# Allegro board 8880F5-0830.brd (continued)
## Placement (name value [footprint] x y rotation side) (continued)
NOREF#2144  -  []  247.25 205.56 90 top
NOREF#2145  -  []  199.59 145.03 90 top
NOREF#2146  -  []  184.47 229.07 90 top
NOREF#2147  -  []  392.04 273.11 90 top
NOREF#2148  -  []  106.03 217.88 90 top
NOREF#2149  -  []  201.66 227.17 90 top
NOREF#2150  -  []  251.62 264.35 90 top
NOREF#2151  -  []  250.73 204.35 90 top
NOREF#2152  -  []  396.55 241.11 0 top
NOREF#2153  -  []  289.01 272.1 0 top
NOREF#2154  -  []  259.65 264.65 90 top
NOREF#2155  -  []  386.53 164.91 90 top
NOREF#2156  -  []  401.87 139.89 0 top
NOREF#2157  -  []  379.73 271.21 90 top
NOREF#2158  -  []  172.08 275.14 90 top
NOREF#2159  -  []  387.39 232.85 0 top
NOREF#2160  -  []  251.62 205.56 0 top
NOREF#2161  -  []  199.84 148.65 90 top
NOREF#2162  -  []  259.59 145.09 0 top
NOREF#2163  -  []  98.53 238.84 0 top
NOREF#2164  -  []  339.33 205.55 0 top
NOREF#2165  -  []  368.03 265.11 0 top
NOREF#2166  -  []  249.6 224.74 90 top
NOREF#2167  -  []  404.24 146.88 0 top
NOREF#2168  -  []  201.23 242.78 90 top
NOREF#2169  -  []  400.24 202.38 90 top
NOREF#2170  -  []  396.55 241.11 0 top
NOREF#2171  -  []  230.73 189.2 0 top
NOREF#2172  -  []  201.91 159.1 90 top
NOREF#2173  -  []  165.8 212.85 0 top
NOREF#2174  -  []  331.94 205.86 90 top
NOREF#2175  -  []  419.9 288.57 90 top
NOREF#2176  -  []  460.89 217.9 90 top
NOREF#2177  -  []  273.59 272.15 90 top
NOREF#2178  -  []  337.9 186.99 0 top
NOREF#2179  -  []  390.94 289.17 90 top
NOREF#2180  -  []  252.6 296.86 0 top
NOREF#2181  -  []  387.39 249.11 0 top
NOREF#2182  -  []  352.25 243.59 90 top
NOREF#2183  -  []  310.43 246.34 90 top
NOREF#2184  -  []  199.33 226.57 90 top
NOREF#2185  -  []  251.38 164.74 90 top
NOREF#2186  -  []  448.94 290.38 90 top
NOREF#2187  -  []  331.22 253.63 0 top
NOREF#2188  -  []  310.43 248.88 90 top
NOREF#2189  -  []  405.93 240.66 90 top
NOREF#2190  -  []  404.24 154.88 0 top
NOREF#2191  -  []  182.82 175.58 90 top
NOREF#2192  -  []  310.73 187.93 0 top
NOREF#2193  -  []  257.9 246.35 90 top
NOREF#2194  -  []  375.73 193.43 0 top
NOREF#2195  -  []  66.26 290.38 90 top
NOREF#2196  -  []  319.33 236.03 90 top
NOREF#2197  -  []  272.25 182.32 90 top
NOREF#2198  -  []  352.55 241.37 0 top
NOREF#2199  -  []  167.7 260.9 90 top
NOREF#2200  -  []  182.57 185.42 0 top
NOREF#2201  -  []  322.23 233.13 90 top
NOREF#2202  -  []  376.23 209.11 0 top
NOREF#2203  -  []  230.41 253.37 90 top
NOREF#2204  -  []  381.74 281.11 0 top
NOREF#2205  -  []  273.81 286.96 90 top
NOREF#2206  -  []  395.2 233.11 0 top
NOREF#2207  -  []  222.11 180.71 0 top
NOREF#2208  -  []  339.97 264.35 90 top
NOREF#2209  -  []  194.09 242.18 90 top
NOREF#2210  -  []  376.23 209.11 0 top
NOREF#2211  -  []  415.61 181.32 90 top
NOREF#2212  -  []  175.7 175.56 90 top
NOREF#2213  -  []  118.45 231.77 0 top
NOREF#2214  -  []  239.33 236.03 90 top
NOREF#2215  -  []  373.32 164.66 90 top
NOREF#2216  -  []  116.01 214.71 0 top
NOREF#2217  -  []  417.7 146.88 0 top
NOREF#2218  -  []  337.09 164.74 90 top
NOREF#2219  -  []  384.36 131.89 0 top
NOREF#2220  -  []  297.83 234.63 90 top
NOREF#2221  -  []  378.33 217.11 0 top
NOREF#2222  -  []  209.33 187.82 90 top
NOREF#2223  -  []  332.83 265.86 90 top
NOREF#2224  -  []  328.62 290.13 90 top
NOREF#2225  -  []  306.92 154.05 0 top
NOREF#2226  -  []  308.91 139.64 0 top
NOREF#2227  -  []  222.11 240.71 0 top
NOREF#2228  -  []  404.15 257.37 0 top
NOREF#2229  -  []  459.28 211.76 0 top
NOREF#2230  -  []  339.33 205.55 0 top
NOREF#2231  -  []  247.25 265.56 0 top
NOREF#2232  -  []  450.03 210.36 0 top
NOREF#2233  -  []  199.33 212.85 90 top
NOREF#2234  -  []  272.24 181.05 90 top
NOREF#2235  -  []  351.34 243.91 0 top
NOREF#2236  -  []  201.49 173.11 0 top
NOREF#2237  -  []  315.7 296.86 0 top
NOREF#2238  -  []  395.2 265.37 0 top
NOREF#2239  -  []  75.98 271.33 90 top
NOREF#2240  -  []  303.56 233.86 90 top
NOREF#2241  -  []  373.68 232.6 0 top
NOREF#2242  -  []  418.38 131.89 0 top
NOREF#2243  -  []  397.38 180.15 90 top
NOREF#2244  -  []  247.57 265.86 90 top
NOREF#2245  -  []  463.11 186.77 0 top
NOREF#2246  -  []  263.71 288.86 0 top
NOREF#2247  -  []  461.86 187.32 0 top
NOREF#2248  -  []  373.87 171.39 0 top
NOREF#2249  -  []  167.7 247.18 90 top
NOREF#2250  -  []  330.73 265.56 90 top
NOREF#2251  -  []  167.7 165.4 90 top
NOREF#2252  -  []  104.18 191.95 90 top
NOREF#2253  -  []  188.08 291.65 90 top
NOREF#2254  -  []  314.71 129.74 90 top
NOREF#2255  -  []  310.73 186.66 0 top
NOREF#2256  -  []  333.4 204.35 90 top
NOREF#2257  -  []  383.09 257.11 0 top
NOREF#2258  -  []  217.41 213.24 0 top
NOREF#2259  -  []  397.8 179.6 90 top
NOREF#2260  -  []  327.7 131.09 90 top
NOREF#2261  -  []  229.21 248.88 0 top
NOREF#2262  -  []  272.25 185.5 0 top
NOREF#2263  -  []  84.04 290.38 90 top
NOREF#2264  -  []  390.69 257.11 0 top
NOREF#2265  -  []  331.06 223.82 90 top
NOREF#2266  -  []  341.63 195.43 90 top
NOREF#2267  -  []  495.08 274.77 90 top
NOREF#2268  -  []  376.23 209.11 0 top
NOREF#2269  -  []  378.75 240.66 90 top
NOREF#2270  -  []  470.71 227 90 top
NOREF#2271  -  []  310.83 164.63 0 top
NOREF#2272  -  []  167.7 138.47 90 top
NOREF#2273  -  []  473.7 219.66 90 top
NOREF#2274  -  []  382.82 163.39 0 top
NOREF#2275  -  []  378.75 224.15 90 top
NOREF#2276  -  []  342.36 223.82 90 top
NOREF#2277  -  []  414.82 249.11 0 top
NOREF#2278  -  []  254.29 265.56 0 top
NOREF#2279  -  []  223.56 173.86 90 top
NOREF#2280  -  []  375.22 180.15 0 top
NOREF#2281  -  []  371.48 224.6 0 top
NOREF#2282  -  []  272.25 189.18 90 top
NOREF#2283  -  []  168.13 213.45 90 top
NOREF#2284  -  []  201.23 241.43 0 top
NOREF#2285  -  []  392.24 196.98 90 top
NOREF#2286  -  []  264.29 280.1 0 top
NOREF#2287  -  []  405.93 272.56 90 top
NOREF#2288  -  []  237.66 164.72 0 top
NOREF#2289  -  []  229.51 247.93 0 top
NOREF#2290  -  []  229.21 188.88 0 top
NOREF#2291  -  []  317.98 223.82 90 top
NOREF#2292  -  []  419.9 240.66 90 top
NOREF#2293  -  []  451.64 222.5 0 top
NOREF#2294  -  []  290.64 288.86 0 top
NOREF#2295  -  []  403.41 209.61 0 top
NOREF#2296  -  []  473.7 176.22 90 top
NOREF#2297  -  []  354.27 138.37 90 top
NOREF#2298  -  []  262.68 224.74 90 top
NOREF#2299  -  []  165.8 240.28 90 top
NOREF#2300  -  []  272.8 145.48 90 top
NOREF#2301  -  []  199.59 158.5 0 top
NOREF#2302  -  []  411.26 163.19 90 top
NOREF#2303  -  []  450.03 191.31 0 top
NOREF#2304  -  []  309.21 247.61 0 top
NOREF#2305  -  []  412.62 297.12 0 top
NOREF#2306  -  []  272.24 182.32 90 top
NOREF#2307  -  []  165.8 144.78 90 top
NOREF#2308  -  []  392.47 256.66 90 top
NOREF#2309  -  []  331.94 204.65 90 top
NOREF#2310  -  []  199.08 254 0 top
NOREF#2311  -  []  330.73 265.56 0 top
NOREF#2312  -  []  274.67 286.96 0 top
NOREF#2313  -  []  449.99 217.9 0 top
NOREF#2314  -  []  319.33 183.63 90 top
NOREF#2315  -  []  271.04 245.5 0 top
NOREF#2316  -  []  230.41 193.37 90 top
NOREF#2317  -  []  250.49 223.52 90 top
NOREF#2318  -  []  229.51 243.41 0 top
NOREF#2319  -  []  295.96 177.06 0 top
NOREF#2320  -  []  301.56 171.46 0 top
NOREF#2321  -  []  392.24 194.78 90 top
NOREF#2322  -  []  218.13 274.06 0 top
NOREF#2323  -  []  184.47 260.9 90 top
NOREF#2324  -  []  394.66 258.64 90 top
NOREF#2325  -  []  221.56 182.89 0 top
NOREF#2326  -  []  184.89 199.99 90 top
NOREF#2327  -  []  369.38 241.11 0 top
NOREF#2328  -  []  321.35 296.86 0 top
NOREF#2329  -  []  184.47 147.28 90 top
NOREF#2330  -  []  301.56 231.46 0 top
NOREF#2331  -  []  250.5 288.86 0 top
NOREF#2332  -  []  216.96 180.71 0 top
NOREF#2333  -  []  405.93 256.82 90 top
NOREF#2334  -  []  262.68 163.52 90 top
NOREF#2335  -  []  271.34 249.5 0 top
NOREF#2336  -  []  312.21 131.64 0 top
NOREF#2337  -  []  167.7 244.98 90 top
NOREF#2338  -  []  182.82 162.12 90 top
NOREF#2339  -  []  403.41 209.61 0 top
NOREF#2340  -  []  265.81 296.86 0 top
NOREF#2341  -  []  415.6 146.88 0 top
NOREF#2342  -  []  253.53 140.14 0 top
NOREF#2343  -  []  167.7 159.65 0 top
NOREF#2344  -  []  310.73 189.2 0 top
NOREF#2345  -  []  341.63 233.83 90 top
NOREF#2346  -  []  283.25 147.43 90 top
NOREF#2347  -  []  175.7 243.88 90 top
NOREF#2348  -  []  296.96 180.71 0 top
NOREF#2349  -  []  342.04 164.72 0 top
NOREF#2350  -  []  272.25 244.23 0 top
NOREF#2351  -  []  101.29 247.16 90 top
NOREF#2352  -  []  229.21 186.34 0 top
NOREF#2353  -  []  310.43 253.37 90 top
NOREF#2354  -  []  115.87 175.44 90 top
NOREF#2355  -  []  396.03 146.88 0 top
NOREF#2356  -  []  331.54 192.73 90 top
NOREF#2357  -  []  471.21 168.33 0 top
NOREF#2358  -  []  383.73 202.38 90 top
NOREF#2359  -  []  110.21 195.15 0 top
NOREF#2360  -  []  459.24 219.3 90 top
NOREF#2361  -  []  313.56 131.64 90 top
NOREF#2362  -  []  328.01 286.96 0 top
NOREF#2363  -  []  385.32 161.49 90 top
NOREF#2364  -  []  201.23 215.35 90 top
NOREF#2365  -  []  263.31 164.74 0 top
NOREF#2366  -  []  192.47 168.6 90 top
NOREF#2367  -  []  343.98 288.86 0 top
NOREF#2368  -  []  298.16 248.49 0 top
NOREF#2369  -  []  250.74 224.72 0 top
NOREF#2370  -  []  242.23 173.13 0 top
NOREF#2371  -  []  247.57 264.65 90 top
NOREF#2372  -  []  352.24 249.18 90 top
NOREF#2373  -  []  352.25 183.59 90 top
NOREF#2374  -  []  271.34 189.5 0 top
NOREF#2375  -  []  229.51 193.69 0 top
NOREF#2376  -  []  115.61 219.13 90 top
NOREF#2377  -  []  425.7 144.98 90 top
NOREF#2378  -  []  231.15 159.63 90 top
NOREF#2379  -  []  263.83 231.63 90 top
NOREF#2380  -  []  449.99 174.46 0 top
NOREF#2381  -  []  409.99 146.93 90 top
NOREF#2382  -  []  265.81 288.86 0 top
NOREF#2383  -  []  272.25 189.82 0 top
NOREF#2384  -  []  272.25 183.59 90 top
NOREF#2385  -  []  166.06 148.4 90 top
NOREF#2386  -  []  338.36 288.91 90 top
NOREF#2387  -  []  406.19 171.64 0 top
NOREF#2388  -  []  175.7 148.38 90 top
NOREF#2389  -  []  279.7 155.38 0 top
NOREF#2390  -  []  215.96 248.49 0 top
NOREF#2391  -  []  518.38 257.36 90 top
NOREF#2392  -  []  260.83 174.63 90 top
NOREF#2393  -  []  330.73 205.55 0 top
NOREF#2394  -  []  177.33 146.68 90 top
NOREF#2395  -  []  410.52 241.11 0 top
NOREF#2396  -  []  211.11 160.4 90 top
NOREF#2397  -  []  155.57 272.6 90 top
NOREF#2398  -  []  185.2 290.01 90 top
NOREF#2399  -  []  415.61 183.52 90 top
NOREF#2400  -  []  259.45 288.86 90 top
NOREF#2401  -  []  248 286.96 0 top
NOREF#2402  -  []  94.68 234.24 0 top
NOREF#2403  -  []  199.59 189.04 90 top
NOREF#2404  -  []  331.05 204.65 90 top
NOREF#2405  -  []  384.36 131.89 0 top
NOREF#2406  -  []  175.7 230.17 90 top
NOREF#2407  -  []  304.82 146.05 0 top
NOREF#2408  -  []  209.59 160.9 90 top
NOREF#2409  -  []  257.9 186.35 90 top
NOREF#2410  -  []  259.33 205.56 0 top
NOREF#2411  -  []  351.04 249.82 0 top
NOREF#2412  -  []  246.63 130.24 90 top
NOREF#2413  -  []  184.47 255.15 90 top
NOREF#2414  -  []  296.96 252.14 0 top
NOREF#2415  -  []  252.51 205.55 0 top
NOREF#2416  -  []  209.08 256.4 90 top
NOREF#2417  -  []  327.25 265.56 90 top
NOREF#2418  -  []  230.41 188.88 90 top
NOREF#2419  -  []  184.47 244.98 90 top
NOREF#2420  -  []  391.8 209.36 0 top
NOREF#2421  -  []  354.08 286.96 90 top
NOREF#2422  -  []  342.68 163.52 90 top
NOREF#2423  -  []  267.84 280.1 0 top
NOREF#2424  -  []  327.57 204.65 90 top
NOREF#2425  -  []  230.43 248.88 90 top
NOREF#2426  -  []  376.15 192.88 90 top
NOREF#2427  -  []  451.64 179.06 0 top
NOREF#2428  -  []  375.73 193.43 90 top
NOREF#2429  -  []  419.9 272.92 90 top
NOREF#2430  -  []  237.57 269.63 90 top
NOREF#2431  -  []  177.33 160.4 90 top
NOREF#2432  -  []  201.49 173.11 90 top
NOREF#2433  -  []  199.33 199.39 90 top
NOREF#2434  -  []  110.21 214.71 0 top
NOREF#2435  -  []  182.57 226.57 0 top
NOREF#2436  -  []  259.33 264.35 90 top
NOREF#2437  -  []  112.67 171.02 0 top
NOREF#2438  -  []  401.89 180.15 0 top
NOREF#2439  -  []  185.2 276.04 90 top
NOREF#2440  -  []  201.23 204.09 90 top
NOREF#2441  -  []  175.8 160.9 90 top
NOREF#2442  -  []  390.69 241.11 0 top
NOREF#2443  -  []  336.77 225.04 90 top
NOREF#2444  -  []  263.71 288.86 0 top
NOREF#2445  -  []  352.25 181.69 0 top
NOREF#2446  -  []  310.73 249.2 0 top
NOREF#2447  -  []  93.76 290.38 90 top
NOREF#2448  -  []  192.47 232.37 90 top
NOREF#2449  -  []  401.89 180.15 0 top
NOREF#2450  -  []  398.53 161.74 90 top
NOREF#2451  -  []  167.7 186.57 0 top
NOREF#2452  -  []  247.25 265.56 90 top
NOREF#2453  -  []  120.21 178.64 0 top
NOREF#2454  -  []  211.11 146.93 90 top
NOREF#2455  -  []  251.62 265.55 0 top
NOREF#2456  -  []  192.47 154.88 90 top
NOREF#2457  -  []  165.8 226.57 90 top
NOREF#2458  -  []  352.55 183.91 0 top
NOREF#2459  -  []  330.73 204.35 90 top
NOREF#2460  -  []  272.55 249.5 0 top
NOREF#2461  -  []  324.65 288.86 0 top
NOREF#2462  -  []  462.06 293.82 90 top
NOREF#2463  -  []  108.01 214.71 0 top
NOREF#2464  -  []  317.66 164.72 0 top
NOREF#2465  -  []  327.25 265.56 0 top
NOREF#2466  -  []  310.43 186.34 90 top
NOREF#2467  -  []  251.33 140.14 0 top
NOREF#2468  -  []  215.96 177.06 0 top
NOREF#2469  -  []  272.24 244.86 90 top
NOREF#2470  -  []  412.88 139.89 0 top
NOREF#2471  -  []  302.11 252.14 0 top
NOREF#2472  -  []  229.21 246.34 0 top
NOREF#2473  -  []  409.74 163.69 90 top
NOREF#2474  -  []  218.13 214.06 0 top
NOREF#2475  -  []  184.47 187.92 90 top
NOREF#2476  -  []  259.33 205.56 90 top
NOREF#2477  -  []  328.96 224.72 0 top
NOREF#2478  -  []  395.07 129.99 0 top
NOREF#2479  -  []  230.43 186.34 0 top
NOREF#2480  -  []  453.88 186.77 0 top
NOREF#2481  -  []  399.07 208.81 90 top
NOREF#2482  -  []  412.79 209.06 90 top
NOREF#2483  -  []  221.56 171.46 0 top
NOREF#2484  -  []  254.29 265.56 90 top
NOREF#2485  -  []  414.25 154.88 0 top
NOREF#2486  -  []  184.47 176.66 90 top
NOREF#2487  -  []  175.7 205.19 90 top
NOREF#2488  -  []  310.41 247.61 90 top
NOREF#2489  -  []  221.56 190.49 0 top
NOREF#2490  -  []  247.57 264.65 90 top
NOREF#2491  -  []  411.01 209.61 0 top
NOREF#2492  -  []  410.84 180.15 90 top
NOREF#2493  -  []  118.45 231.77 0 top
NOREF#2494  -  []  257.9 246.99 0 top
NOREF#2495  -  []  175.8 215.25 90 top
NOREF#2496  -  []  375.73 199.18 90 top
NOREF#2497  -  []  388.43 180.15 0 top
NOREF#2498  -  []  194.09 201.29 90 top
NOREF#2499  -  []  302.11 192.14 0 top
NOREF#2500  -  []  419.47 289.12 90 top
NOREF#2501  -  []  200.98 256.5 90 top
NOREF#2502  -  []  392.47 288.67 90 top
NOREF#2503  -  []  409.74 180.2 90 top
NOREF#2504  -  []  215.96 188.49 0 top
NOREF#2505  -  []  351.04 249.18 0 top
NOREF#2506  -  []  175.7 232.37 90 top
NOREF#2507  -  []  397.8 146.33 90 top
NOREF#2508  -  []  343.2 232.26 90 top
NOREF#2509  -  []  334.61 204.65 90 top
NOREF#2510  -  []  410.78 131.89 0 top
NOREF#2511  -  []  172.08 289.11 90 top
NOREF#2512  -  []  248.61 290.13 90 top
NOREF#2513  -  []  246.63 142.04 0 top
NOREF#2514  -  []  371.73 297.12 0 top
NOREF#2515  -  []  310.73 183.41 0 top
NOREF#2516  -  []  106.76 222.88 0 top
NOREF#2517  -  []  167.7 206.29 90 top
NOREF#2518  -  []  240.94 211.63 90 top
NOREF#2519  -  []  418.12 257.42 90 top
NOREF#2520  -  []  167.7 219.75 90 top
NOREF#2521  -  []  400.54 171.64 0 top
NOREF#2522  -  []  308.14 296.86 0 top
NOREF#2523  -  []  253.4 265.55 0 top
NOREF#2524  -  []  380.59 239.21 0 top
NOREF#2525  -  []  240.83 254.63 0 top
NOREF#2526  -  []  330.17 223.82 90 top
NOREF#2527  -  []  412.62 273.37 0 top
NOREF#2528  -  []  309.51 186.66 0 top
NOREF#2529  -  []  192.57 242.68 90 top
NOREF#2530  -  []  256.45 164.74 0 top
NOREF#2531  -  []  165.8 158.5 90 top
NOREF#2532  -  []  246.67 288.16 90 top
NOREF#2533  -  []  330.74 164.72 0 top
NOREF#2534  -  []  405.93 224.66 90 top
NOREF#2535  -  []  456.08 195.91 0 top
NOREF#2536  -  []  262.36 223.82 90 top
NOREF#2537  -  []  184.89 213.45 90 top
NOREF#2538  -  []  184.47 247.18 90 top
NOREF#2539  -  []  453.88 171.53 0 top
NOREF#2540  -  []  321.82 167.13 90 top
NOREF#2541  -  []  112.16 238.84 0 top
NOREF#2542  -  []  201.49 174.46 90 top
NOREF#2543  -  []  260.74 143.19 0 top
NOREF#2544  -  []  252.43 132.14 0 top
NOREF#2545  -  []  118.7 222.88 0 top
NOREF#2546  -  []  450.03 182.17 0 top
NOREF#2547  -  []  230.73 186.66 0 top
NOREF#2548  -  []  251.86 192.43 90 top
NOREF#2549  -  []  271.04 184.23 0 top
NOREF#2550  -  []  277.17 288.86 0 top
NOREF#2551  -  []  184.47 151.68 90 top
NOREF#2552  -  []  463.61 214.96 0 top
NOREF#2553  -  []  211.11 173.86 90 top
NOREF#2554  -  []  127.99 214.79 0 top
NOREF#2555  -  []  167.7 219.75 90 top
NOREF#2556  -  []  128.24 171.1 0 top
NOREF#2557  -  []  302.49 296.86 0 top
NOREF#2558  -  []  167.7 256.5 90 top
NOREF#2559  -  []  96.58 195.15 0 top
NOREF#2560  -  []  279.7 155.38 0 top
NOREF#2561  -  []  322.23 173.13 90 top
NOREF#2562  -  []  456.08 171.53 0 top
NOREF#2563  -  []  230.41 246.34 90 top
NOREF#2564  -  []  396.55 289.12 0 top
NOREF#2565  -  []  200.98 260.9 90 top
NOREF#2566  -  []  470.71 183.57 90 top
NOREF#2567  -  []  230.43 246.34 90 top
NOREF#2568  -  []  199.59 145.03 0 top
NOREF#2569  -  []  518.38 273.87 90 top
NOREF#2570  -  []  278.6 147.38 0 top
NOREF#2571  -  []  398.65 225.11 0 top
NOREF#2572  -  []  394.05 239.21 0 top
R1  NC/1M-1-S4  [R0402]  221.23 227.84 180 bottom
R2  NC/1M-1-S4  [R0402]  218.95 227.84 0 bottom
R3  NC/100K-1-S4  [R0402]  184.15 131.06 180 bottom
R4  NC/100K-1-S4  [R0402]  181.61 131.06 180 bottom
R5  0-5-S4  [R0402]  222.38 272.16 270 bottom
R6  1M-1-S4  [R0402]  222.38 274.32 270 bottom
R7  49.9-1-S4  [R0402]  349.4 299.66 180 bottom
R8  49.9-1-S4  [R0402]  351.55 299.66 180 bottom
R9  49.9-1-S4  [R0402]  349.4 286.07 180 bottom
R10  49.9-1-S4  [R0402]  351.55 286.07 180 bottom
R11  49.9-1-S4  [R0402]  335.94 299.66 180 bottom
R12  49.9-1-S4  [R0402]  338.09 299.66 180 bottom
R13  49.9-1-S4  [R0402]  335.94 286.07 180 bottom
R14  49.9-1-S4  [R0402]  338.09 286.07 180 bottom
R15  49.9-1-S4  [R0402]  322.48 299.66 180 bottom
R16  49.9-1-S4  [R0402]  324.62 299.66 180 bottom
R17  49.9-1-S4  [R0402]  322.48 286.07 180 bottom
R18  49.9-1-S4  [R0402]  324.62 286.07 180 bottom
R19  49.9-1-S4  [R0402]  287.88 269.3 0 bottom
R20  49.9-1-S4  [R0402]  285.74 269.3 0 bottom
R21  49.9-1-S4  [R0402]  287.88 282.89 0 bottom
R22  49.9-1-S4  [R0402]  285.74 282.89 0 bottom
R23  49.9-1-S4  [R0402]  309.27 299.66 180 bottom
R24  49.9-1-S4  [R0402]  311.42 299.66 180 bottom
R25  49.9-1-S4  [R0402]  309.27 286.07 180 bottom
R26  49.9-1-S4  [R0402]  311.42 286.07 180 bottom
R27  49.9-1-S4  [R0402]  296.06 299.66 180 bottom
R28  49.9-1-S4  [R0402]  298.21 299.66 180 bottom
R29  49.9-1-S4  [R0402]  296.06 286.07 180 bottom
R30  49.9-1-S4  [R0402]  298.21 286.07 180 bottom
R31  49.9-1-S4  [R0402]  282.6 299.66 180 bottom
R32  49.9-1-S4  [R0402]  284.75 299.66 180 bottom
R33  49.9-1-S4  [R0402]  282.6 286.07 180 bottom
R34  49.9-1-S4  [R0402]  284.75 286.07 180 bottom
R37  49.9-1-S4  [R0402]  269.14 286.07 180 bottom
R38  49.9-1-S4  [R0402]  271.28 286.07 180 bottom
R39  49.9-1-S4  [R0402]  255.93 299.66 180 bottom
R40  49.9-1-S4  [R0402]  258.08 299.66 180 bottom
R41  49.9-1-S4  [R0402]  255.93 286.07 180 bottom
R42  49.9-1-S4  [R0402]  258.08 286.07 180 bottom
R43  49.9-1-S4  [R0402]  164.91 258.67 90 bottom
R44  49.9-1-S4  [R0402]  164.91 256.53 90 bottom
R45  49.9-1-S4  [R0402]  198.44 231.24 90 bottom
R46  49.9-1-S4  [R0402]  198.44 229.1 90 bottom
R47  49.9-1-S4  [R0402]  178.5 217.52 90 bottom
R48  49.9-1-S4  [R0402]  178.5 215.38 90 bottom
R49  49.9-1-S4  [R0402]  164.91 217.52 90 bottom
R50  49.9-1-S4  [R0402]  164.91 215.38 90 bottom
R51  49.9-1-S4  [R0402]  195.26 231.24 90 bottom
R52  49.9-1-S4  [R0402]  195.26 229.1 90 bottom
R53  49.9-1-S4  [R0402]  181.67 231.24 90 bottom
R54  49.9-1-S4  [R0402]  181.67 229.1 90 bottom
R55  49.9-1-S4  [R0402]  212.03 244.96 90 bottom
R56  49.9-1-S4  [R0402]  212.03 242.81 90 bottom
R57  49.9-1-S4  [R0402]  198.44 244.96 90 bottom
R58  49.9-1-S4  [R0402]  198.44 242.81 90 bottom
R59  49.9-1-S4  [R0402]  178.5 231.24 90 bottom
R60  49.9-1-S4  [R0402]  178.5 229.1 90 bottom
R61  49.9-1-S4  [R0402]  164.91 231.24 90 bottom
R62  49.9-1-S4  [R0402]  164.91 229.1 90 bottom
R63  49.9-1-S4  [R0402]  178.5 244.96 90 bottom
R64  49.9-1-S4  [R0402]  178.5 242.81 90 bottom
R65  49.9-1-S4  [R0402]  181.67 244.96 90 bottom
R66  49.9-1-S4  [R0402]  181.67 242.81 90 bottom
R67  49.9-1-S4  [R0402]  239.37 285.81 0 bottom
R68  49.9-1-S4  [R0402]  237.22 285.81 0 bottom
R69  49.9-1-S4  [R0402]  239.37 299.4 0 bottom
R70  49.9-1-S4  [R0402]  237.22 299.4 0 bottom
R71  49.9-1-S4  [R0402]  195.26 258.67 90 bottom
R72  49.9-1-S4  [R0402]  195.26 256.53 90 bottom
R73  49.9-1-S4  [R0402]  181.67 258.67 90 bottom
R74  49.9-1-S4  [R0402]  181.67 256.53 90 bottom
R75  49.9-1-S4  [R0402]  211.77 258.67 90 bottom
R76  49.9-1-S4  [R0402]  211.77 256.53 90 bottom
R77  49.9-1-S4  [R0402]  198.18 258.67 90 bottom
R78  49.9-1-S4  [R0402]  198.18 256.53 90 bottom
R79  49.9-1-S4  [R0402]  178.5 258.67 90 bottom
R80  49.9-1-S4  [R0402]  178.5 256.53 90 bottom
R82  4.7K-1-S4-WA  [R0402]  122.62 241.1 180 bottom
R83  4.7K-1-S4-WA  [R0402]  96.77 233.43 180 bottom
R84  4.7K-1-S4-WA  [R0402]  96.77 241.05 180 bottom
R85  100K-1-S4  [R0402]  113.79 230.12 180 bottom
R86  4.7K-1-S4-WA  [R0402]  93.33 207.46 180 bottom
R87  4.7K-1-S4-WA  [R0402]  104.14 203.31 180 bottom
R88  4.7K-1-S4-WA  [R0402]  101.6 203.31 180 bottom
R89  4.7K-1-S4-WA  [R0402]  89.03 207.41 0 bottom
R90  4.7K-1-S4-WA  [R0402]  101.6 215.5 180 bottom
R91  4.7K-1-S4-WA  [R0402]  99.06 215.5 180 bottom
R92  4.7K-1-S4-WA  [R0402]  96.52 215.5 180 bottom
R93  4.7K-1-S4-WA  [R0402]  93.33 221.18 180 bottom
R94  4.7K-1-S4-WA  [R0402]  104.25 216.86 0 bottom
R95  4.7K-1-S4-WA  [R0402]  101.7 216.91 180 bottom
R96  4.7K-1-S4-WA  [R0402]  89.27 221.18 0 bottom
R97  4.7K-1-S4-WA  [R0402]  101.7 229.1 180 bottom
R98  4.7K-1-S4-WA  [R0402]  99.16 229.1 180 bottom
R99  4.7K-1-S4-WA  [R0402]  96.62 229.1 180 bottom
R100  49.9-1-S4  [R0402]  164.91 244.96 90 bottom
R101  49.9-1-S4  [R0402]  164.91 242.81 90 bottom
R102  49.9-1-S4  [R0402]  212.03 231.24 90 bottom
R103  49.9-1-S4  [R0402]  212.03 229.1 90 bottom
R104  49.9-1-S4  [R0402]  195.26 244.96 90 bottom
R105  49.9-1-S4  [R0402]  195.26 242.81 90 bottom
R117  1K-1-S4  [R0402]  127.2 241.1 180 bottom
R118  NC/0-5-S4  [R0402]  230.41 245.39 180 bottom
R119  4.7K-1-S4-WA  [R0402]  127.25 233.43 0 bottom
R120  4.7K-1-S4-WA  [R0402]  127.25 225.81 0 bottom
R125  0-5-S4  [R0402]  123.19 224.54 180 bottom
R126  0-5-S4  [R0402]  127.25 224.54 180 bottom
R127  0-5-S4  [R0402]  122.94 216.92 180 bottom
R128  0-5-S4  [R0402]  127.51 216.92 180 bottom
R129  0-5-S4  [R0402]  221.23 229.11 180 bottom
R130  0-5-S4  [R0402]  218.95 229.11 0 bottom
R131  50-0.1-S4-HF-VI  [R0402]  223.77 243.33 90 bottom
R132  50-0.1-S4-HF-VI  [R0402]  216.15 243.33 90 bottom
R133  0-5-S4  [R0402]  222.38 276.48 90 bottom
RB1  10K-1-S6  [R0603]  212.47 13.59 0 bottom
RB2  10K-1-S6  [R0603]  212.47 12.06 0 bottom
S1_I2C  HDR-4X1-MR-A  [JP_4P_100_R90_V1]  62.99 209.04 270 top
S1_RST_N  HDR-2X1-M  [JP_2P_100]  115.82 232.41 270 bottom
S2_I2C  HDR-4X1-MR-A  [JP_4P_100_R90_V1]  497.33 203.45 270 top
S2_RST_N  HDR-2X1-M  [JP_2P_100]  463.04 233.43 90 bottom
S3_I2C  HDR-4X1-MR-A  [JP_4P_100_R90_V1]  75.69 209.04 270 top
S3_RST_N  HDR-2X1-M  [JP_2P_100]  116.08 188.72 270 bottom
S4_I2C  HDR-4X1-MR-A  [JP_4P_100_R90_V1]  511.3 203.45 270 top
S4_RST_N  HDR-2X1-M  [JP_2P_100]  463.04 189.99 90 bottom
SB1  SHORT  [DEFAULT_SHORT_SMALL]  402.59 11.04 90 top
SB2  SHORT  [DEFAULT_SHORT_SMALL]  328.93 417.83 270 top
SB3  SHORT  [DEFAULT_SHORT_SMALL]  255.27 11.71 90 top
SB8  SHORT  [DEFAULT_SHORT_SMALL]  179.07 418.32 270 top
SCREW1  V93KMFHOLE  [PG_VG93K_F_FULLOUTLINE]  290.83 214.63 0 top
SH1  SHORT  [DEFAULT_SHORT_SMALL]  185.19 290.72 0 top
SH2  SHORT  [DEFAULT_SHORT_SMALL]  187.14 290.72 0 top
SH3  SHORT  [DEFAULT_SHORT_SMALL]  175.35 290.72 0 top
SH4  SHORT  [DEFAULT_SHORT_SMALL]  173.4 290.85 180 top
SH5  SHORT  [DEFAULT_SHORT_SMALL]  118.2 289.45 0 top
SH6  SHORT  [DEFAULT_SHORT_SMALL]  116.25 289.58 180 top
SH7  SHORT  [DEFAULT_SHORT_SMALL]  168.68 290.72 0 top
SH8  SHORT  [DEFAULT_SHORT_SMALL]  156.89 290.85 180 top
SH9  SHORT  [DEFAULT_SHORT_SMALL]  170.63 290.72 0 top
SH10  SHORT  [DEFAULT_SHORT_SMALL]  158.84 290.72 0 top
SH11  SHORT  [DEFAULT_SHORT_SMALL]  173.4 274.34 180 top
SH12  SHORT  [DEFAULT_SHORT_SMALL]  185.19 274.21 0 top
SH13  SHORT  [DEFAULT_SHORT_SMALL]  203.14 290.72 0 top
SH14  SHORT  [DEFAULT_SHORT_SMALL]  201.19 290.72 0 top
SH15  SHORT  [DEFAULT_SHORT_SMALL]  189.4 290.85 180 top
SH16  SHORT  [DEFAULT_SHORT_SMALL]  191.35 290.72 0 top
SH17  SHORT  [DEFAULT_SHORT_SMALL]  156.89 274.34 180 top
SH18  SHORT  [DEFAULT_SHORT_SMALL]  168.68 274.21 0 top
SH19  SHORT  [DEFAULT_SHORT_SMALL]  99.42 246.45 0 top
SH20  SHORT  [DEFAULT_SHORT_SMALL]  101.62 246.45 0 top
SH21  SHORT  [DEFAULT_SHORT_SMALL]  94.56 246.5 0 top
SH22  SHORT  [DEFAULT_SHORT_SMALL]  96.76 246.5 0 top
SH23  SHORT  [DEFAULT_SHORT_SMALL]  201.19 274.21 0 top
SH24  SHORT  [DEFAULT_SHORT_SMALL]  203.37 274.08 180 top
SH25  SHORT  [DEFAULT_SHORT_SMALL]  175.35 274.21 0 top
SH26  SHORT  [DEFAULT_SHORT_SMALL]  187.14 274.21 0 top
SH27  SHORT  [DEFAULT_SHORT_SMALL]  158.84 274.21 0 top
SH28  SHORT  [DEFAULT_SHORT_SMALL]  170.63 274.21 0 top
SITE1  CU/HX8880-F05-LQFP176-20X20  [SK_LQFP176P_0P4MM_JG_HX8880]  250.83 244.63 90 top
SITE2  CU/HX8880-F05-LQFP176-20X20  [SK_LQFP176P_0P4MM_JG_HX8880]  330.83 244.63 90 top
SITE3  CU/HX8880-F05-LQFP176-20X20  [SK_LQFP176P_0P4MM_JG_HX8880]  250.83 184.63 90 top
SITE4  CU/HX8880-F05-LQFP176-20X20  [SK_LQFP176P_0P4MM_JG_HX8880]  330.83 184.63 90 top
SKB  Socket_Base_M5_140x140  [SOCKET_BASE_140X140_565100]  290.83 214.63 0 top
TP_AUXVCC  TP01  [TP_040_T]  101.29 247.61 180 top
TP_AVDD11_RX  TP01  [TP_040_T]  158.96 292.1 180 top
TP_AVDD11_XTAL  TP01  [TP_040_T]  201.21 275.59 0 top
TP_AVDD18_RX  TP01  [TP_040_T]  168.7 292.1 0 top
TP_PLL_M_VDD33  TP01  [TP_040_T]  201.21 292.1 0 top
TP_PLL_TX_VDD33  TP01  [TP_040_T]  191.48 292.1 180 top
TP_VCC3V3  TP01  [TP_040_T]  96.42 247.66 180 top
TP_VDD_IO_33  TP01  [TP_040_T]  175.47 292.1 180 top
TP_VDD_TXREG_33_B  TP01  [TP_040_T]  168.7 275.59 0 top
TP_VDD_TXREG_33_T  TP01  [TP_040_T]  158.96 275.59 180 top
TP_VDDA_33_LV  TP01  [TP_040_T]  185.21 292.1 0 top
TP_VDDC_11  TP01  [TP_040_T]  118.32 290.83 180 top
TP_VDDTXPST_11_B  TP01  [TP_040_T]  185.21 275.59 0 top
TP_VDDTXPST_11_T  TP01  [TP_040_T]  175.47 275.59 180 top
TP_XTAL_IN  TP01  [TP_040_T]  226.85 271.67 0 top
TP_XTAL_OUT  TP01  [TP_040_T]  226.85 276.97 0 top
TPL1  TPL01  [TPL_040_014_TB]  73.41 239.01 0 top
TPL2  TPL01  [TPL_040_014_TB]  78.49 244.09 0 top
TPL3  TPL01  [TPL_040_014_TB]  68.33 228.85 0 top
TPL4  TPL01  [TPL_040_014_TB]  68.33 239.01 0 top
TPL5  TPL01  [TPL_040_014_TB]  73.41 244.09 0 top
TPL6  TPL01  [TPL_040_014_TB]  68.33 233.93 0 top
TPL7  TPL01  [TPL_040_014_TB]  78.49 233.93 0 top
TPL8  TPL01  [TPL_040_014_TB]  73.41 233.93 0 top
TPL9  TPL01  [TPL_040_014_TB]  68.33 244.09 0 top
TPL10  TPL01  [TPL_040_014_TB]  78.49 239.01 0 top
TPL11  TPL01  [TPL_040_014_TB]  73.41 218.69 0 top
TPL12  TPL01  [TPL_040_014_TB]  78.49 218.69 0 top
TPL13  TPL01  [TPL_040_014_TB]  83.57 223.77 0 top
TPL14  TPL01  [TPL_040_014_TB]  83.57 218.69 0 top
TPL15  TPL01  [TPL_040_014_TB]  73.41 228.85 0 top
TPL16  TPL01  [TPL_040_014_TB]  68.33 223.77 0 top
TPL17  TPL01  [TPL_040_014_TB]  68.33 218.69 0 top
TPL18  TPL01  [TPL_040_014_TB]  78.49 223.77 0 top
TPL19  TPL01  [TPL_040_014_TB]  73.41 223.77 0 top
TPL20  TPL01  [TPL_040_014_TB]  78.49 228.85 0 top
TPL21  TPL01  [TPL_040_014_TB]  452.63 249.17 0 top
TPL22  TPL01  [TPL_040_014_TB]  452.63 259.33 0 top
TPL23  TPL01  [TPL_040_014_TB]  452.63 264.41 0 top
TPL24  TPL01  [TPL_040_014_TB]  452.63 254.25 0 top
TPL25  TPL01  [TPL_040_014_TB]  452.63 244.09 0 top
TPL26  TPL01  [TPL_040_014_TB]  457.71 244.09 0 top
TPL27  TPL01  [TPL_040_014_TB]  452.63 269.49 0 top
TPL28  TPL01  [TPL_040_014_TB]  457.71 249.17 0 top
TPL29  TPL01  [TPL_040_014_TB]  457.71 269.49 0 top
TPL30  TPL01  [TPL_040_014_TB]  457.71 264.41 0 top
TPL31  TPL01  [TPL_040_014_TB]  457.71 259.33 0 top
TPL32  TPL01  [TPL_040_014_TB]  457.71 254.25 0 top
TPL33  TPL01  [TPL_040_014_TB]  462.79 244.09 0 top
TPL34  TPL01  [TPL_040_014_TB]  467.87 249.17 0 top
TPL35  TPL01  [TPL_040_014_TB]  467.87 244.09 0 top
TPL36  TPL01  [TPL_040_014_TB]  462.79 249.17 0 top
TPL37  TPL01  [TPL_040_014_TB]  462.79 269.49 0 top
TPL38  TPL01  [TPL_040_014_TB]  462.79 259.33 0 top
TPL39  TPL01  [TPL_040_014_TB]  462.79 254.25 0 top
TPL40  TPL01  [TPL_040_014_TB]  462.79 264.41 0 top
U1  SOLDER-DIP8-SOCKET  [DIP8_300X100_RLPIN]  104.66 205.54 90 bottom
U2  SOLDER-DIP8-SOCKET  [DIP8_300X100_RLPIN]  104.76 219.15 90 bottom
UB1  AT24C04C-SSHM-SO8  [SO8_215X127MM]  218.44 13.97 180 bottom
UF1  MX25L4006EM2I-12G-SOP8  [SOCKET_CODE]  104.66 205.54 270 top
UF2  MX25L4006EM2I-12G-SOP8  [SOCKET_CODE]  104.75 219.2 270 top
UNK2C3  0.1U-16-X-S4-MU  [C0402]  289.81 132.08 180 bottom
UNK2C4  0.1U-16-X-S4-MU  [C0402]  287.27 132.08 180 bottom
UNK2C5  22P-50-N-S4-AVX  [C0402]  301.21 277.48 90 bottom
UNK2C6  22P-50-N-S4-AVX  [C0402]  301.21 271.16 270 bottom
UNK2C7  0.1U-16-X-S4-MU  [C0402]  468.12 235.71 180 bottom
UNK2C8  0.1U-16-X-S4-MU  [C0402]  475.39 204.98 0 bottom
UNK2C9  0.1U-16-X-S4-MU  [C0402]  475.49 218.59 0 bottom
UNK2CA1  NC/10U-10-X6S-S6-MU  [C0603]  462.91 293.37 0 bottom
UNK2CA2  NC/47U-10-X5R-S8-TDK  [C0805]  463.02 295.27 0 bottom
UNK2CA3  NC/10U-10-X6S-S6-MU  [C0603]  451.49 293.37 180 bottom
UNK2CA4  NC/47U-10-X5R-S8-TDK  [C0805]  451.38 295.27 180 bottom
UNK2CA5  NC/10U-10-X6S-S6-MU  [C0603]  484.5 293.37 180 bottom
UNK2CA6  NC/47U-10-X5R-S8-TDK  [C0805]  484.4 295.27 180 bottom
UNK2CA7  NC/10U-10-X6S-S6-MU  [C0603]  462.91 276.86 0 bottom
UNK2CA8  NC/47U-10-X5R-S8-TDK  [C0805]  463.02 278.76 0 bottom
UNK2CA9  NC/10U-10-X6S-S6-MU  [C0603]  451.49 276.86 180 bottom
UNK2CA10  NC/47U-10-X5R-S8-TDK  [C0805]  451.38 278.76 180 bottom
UNK2CA11  NC/10U-10-X6S-S6-MU  [C0603]  495.93 276.86 0 bottom
UNK2CA12  NC/47U-10-X5R-S8-TDK  [C0805]  496.04 278.76 0 bottom
UNK2CA13  NC/47U-10-X5R-S8-TDK  [C0805]  479.53 295.27 0 bottom
UNK2CA14  NC/10U-10-X6S-S6-MU  [C0603]  479.42 293.37 0 bottom
UNK2CA15  NC/47U-10-X5R-S8-TDK  [C0805]  467.89 295.27 180 bottom
UNK2CA16  NC/10U-10-X6S-S6-MU  [C0603]  468 293.37 180 bottom
UNK2CA17  NC/47U-10-X5R-S8-TDK  [C0805]  479.53 278.76 0 bottom
UNK2CA18  NC/10U-10-X6S-S6-MU  [C0603]  479.42 276.86 0 bottom
UNK2CA19  NC/47U-10-X5R-S8-TDK  [C0805]  91.09 249.81 180 bottom
UNK2CA20  NC/10U-10-X6S-S6-MU  [C0603]  91.19 247.9 180 bottom
UNK2CA21  10U-10-X6S-S6-MU  [C0603]  462.91 290.83 0 bottom
UNK2CA22  10U-10-X6S-S6-MU  [C0603]  451.49 290.83 180 bottom
UNK2CA23  10U-10-X6S-S6-MU  [C0603]  484.5 290.83 180 bottom
UNK2CA24  10U-10-X6S-S6-MU  [C0603]  462.91 274.32 0 bottom
UNK2CA25  10U-10-X6S-S6-MU  [C0603]  451.49 274.32 180 bottom
UNK2CA26  10U-10-X6S-S6-MU  [C0603]  495.93 274.32 0 bottom
UNK2CA27  10U-10-X6S-S6-MU  [C0603]  479.42 290.83 0 bottom
UNK2CA28  10U-10-X6S-S6-MU  [C0603]  468 290.83 180 bottom
UNK2CA29  10U-10-X6S-S6-MU  [C0603]  479.42 274.32 0 bottom
UNK2CA30  NC/47U-10-X5R-S8-TDK  [C0805]  86.22 249.86 180 bottom
UNK2CA31  10U-10-X6S-S6-MU  [C0603]  86.32 247.96 180 bottom
UNK2CA32  NC/10U-10-X6S-S6-MU  [C0603]  512.44 293.37 0 bottom
UNK2CA33  NC/47U-10-X5R-S8-TDK  [C0805]  512.55 295.27 0 bottom
UNK2CA34  10U-10-X6S-S6-MU  [C0603]  512.44 290.83 0 bottom
UNK2CA35  NC/10U-10-X6S-S6-MU  [C0603]  484.5 276.86 180 bottom
UNK2CA36  NC/47U-10-X5R-S8-TDK  [C0805]  484.4 278.76 180 bottom
UNK2CA37  10U-10-X6S-S6-MU  [C0603]  484.5 274.32 180 bottom
UNK2CA38  NC/10U-10-X6S-S6-MU  [C0603]  468 276.86 180 bottom
UNK2CA39  NC/47U-10-X5R-S8-TDK  [C0805]  467.89 278.76 180 bottom
UNK2CA40  10U-10-X6S-S6-MU  [C0603]  468 274.32 180 bottom
UNK2CC1  0.47U-10-X6S-S2-TY  [C0201]  317.98 224.12 90 bottom
UNK2CC2  4.7U-10-X6T-S4-MU  [C0402]  316.32 222.4 270 bottom
UNK2CC4  0.47U-10-X6S-S2-TY  [C0201]  309.81 247.93 0 bottom
UNK2CC6  0.47U-10-X6S-S2-TY  [C0201]  330.17 224.12 90 bottom
UNK2CC7  0.47U-10-X6S-S2-TY  [C0201]  309.81 246.66 0 bottom
UNK2CC8  0.47U-10-X6S-S2-TY  [C0201]  343.63 224.12 90 bottom
UNK2CC9  0.47U-10-X6S-S2-TY  [C0201]  334.61 266.16 270 bottom
UNK2CC11  0.47U-10-X6S-S2-TY  [C0201]  331.06 224.12 90 bottom
UNK2CC13  0.47U-10-X6S-S2-TY  [C0201]  336.77 224.12 90 bottom
UNK2CC15  4.7U-2.5-X6S-S2-MU  [C0201]  339.65 264.95 90 bottom
UNK2CC16  NC/4.7U-2.5-X6S-S2-MU  [C0201]  351.64 249.5 0 bottom
UNK2CC17  4.7U-2.5-X6S-S2-MU  [C0201]  309.81 253.69 0 bottom
UNK2CC19  0.47U-10-X6S-S2-TY  [C0201]  332.83 266.16 270 bottom
UNK2CC20  4.7U-10-X6T-S4-MU  [C0402]  334.11 267.66 0 bottom
UNK2CC22  0.47U-10-X6S-S2-TY  [C0201]  331.05 266.16 270 bottom
UNK2CC23  4.7U-10-X6T-S4-MU  [C0402]  330.34 253.09 270 bottom
UNK2CC25  0.47U-10-X6S-S2-TY  [C0201]  352.85 245.18 180 bottom
UNK2CC26  0.47U-10-X6S-S2-TY  [C0201]  333.72 266.16 270 bottom
UNK2CC27  0.47U-10-X6S-S2-TY  [C0201]  352.85 249.5 180 bottom
UNK2CC28  0.47U-10-X6S-S2-TY  [C0201]  339.65 266.16 270 bottom
UNK2CC29  0.47U-10-X6S-S2-TY  [C0201]  311.03 253.69 180 bottom
UNK2CC30  0.47U-10-X6S-S2-TY  [C0201]  309.81 243.41 0 bottom
UNK2CC31  0.47U-10-X6S-S2-TY  [C0201]  329.28 224.12 90 bottom
UNK2CC32  0.47U-10-X6S-S2-TY  [C0201]  342.36 224.12 90 bottom
UNK2CC33  0.47U-10-X6S-S2-TY  [C0201]  352.85 243.91 180 bottom
UNK2CC34  0.47U-10-X6S-S2-TY  [C0201]  331.94 266.16 270 bottom
UNK2CC35  0.47U-10-X6S-S2-TY  [C0201]  352.85 241.37 180 bottom
UNK2CC36  0.47U-10-X6S-S2-TY  [C0201]  352.85 242.64 180 bottom
UNK2CC37  0.47U-10-X6S-S2-TY  [C0201]  327.57 264.95 90 bottom
UNK2CC38  NC/4.7U-2.5-X6S-S2-MU  [C0201]  327.57 266.16 270 bottom
UNK2CC39  0.47U-10-X6S-S2-TY  [C0201]  311.03 249.2 180 bottom
UNK2CC40  4.7U-2.5-X6S-S2-MU  [C0201]  338.5 246.67 180 bottom
UNK2CC41  4.7U-2.5-X6S-S2-MU  [C0201]  309.81 249.2 0 bottom
UNK2CC42  4.7U-2.5-X6S-S2-MU  [C0201]  331.54 253.03 90 bottom
UNK2CD1  0.1U-10-X7R-S2-MU  [C0201]  317.98 225.34 270 top
UNK2CD3  0.1U-10-X7R-S2-MU  [C0201]  351.64 241.37 0 top
UNK2CD4  0.1U-10-X7R-S2-MU  [C0201]  334.61 264.95 90 top
UNK2CD5  0.1U-10-X7R-S2-MU  [C0201]  343.63 225.34 270 top
UNK2CD6  0.1U-10-X7R-S2-MU  [C0201]  311.03 246.66 180 top
UNK2CD7  0.1U-10-X7R-S2-MU  [C0201]  351.64 242.64 0 top
UNK2CD8  0.1U-10-X7R-S2-MU  [C0201]  331.06 225.34 270 top
UNK2CD9  0.1U-10-X7R-S2-MU  [C0201]  336.77 225.34 270 top
UNK2CD10  0.1U-10-X7R-S2-MU  [C0201]  351.64 249.5 0 top
UNK2CD11  0.1U-10-X7R-S2-MU  [C0201]  339.65 264.95 90 top
UNK2CD12  0.1U-10-X7R-S2-MU  [C0201]  311.03 253.69 180 top
UNK2CD13  0.1U-10-X7R-S2-MU  [C0201]  332.83 264.95 90 top
UNK2CD14  0.1U-10-X7R-S2-MU  [C0201]  331.05 264.95 90 top
UNK2CD15  0.1U-10-X7R-S2-MU  [C0201]  351.64 245.18 0 top
UNK2CD16  0.1U-10-X7R-S2-MU  [C0201]  333.72 264.95 90 top
UNK2CD17  0.1U-10-X7R-S2-MU  [C0201]  311.03 247.93 180 top
UNK2CD18  0.1U-10-X7R-S2-MU  [C0201]  331.94 264.95 90 top
UNK2CD19  0.1U-10-X7R-S2-MU  [C0201]  311.03 243.41 180 top
UNK2CD20  0.1U-10-X7R-S2-MU  [C0201]  351.64 243.91 0 top
UNK2CD21  0.1U-10-X7R-S2-MU  [C0201]  342.36 225.34 270 top
UNK2CD22  0.1U-10-X7R-S2-MU  [C0201]  329.28 225.34 270 top
UNK2CD23  0.1U-10-X7R-S2-MU  [C0201]  330.17 225.34 270 top
UNK2CD24  0.1U-10-X7R-S2-MU  [C0201]  327.57 264.95 90 top
UNK2CD25  0.1U-10-X7R-S2-MU  [C0201]  311.03 249.2 180 top
UNK2GND1  TP01  [TP_040_T]  450.43 295.27 0 top
UNK2GND2  TP01  [TP_040_T]  463.97 295.27 180 top
UNK2GND3  TP01  [TP_040_T]  483.45 295.27 0 top
UNK2GND4  TP01  [TP_040_T]  450.43 278.76 0 top
UNK2GND5  TP01  [TP_040_T]  463.97 278.76 180 top
UNK2GND6  TP01  [TP_040_T]  483.45 278.76 0 top
UNK2GND7  TP01  [TP_040_T]  480.48 295.27 180 top
UNK2GND8  TP01  [TP_040_T]  466.94 295.27 0 top
UNK2GND9  TP01  [TP_040_T]  480.48 278.76 180 top
UNK2GND10  TP01  [TP_040_T]  90.11 249.76 0 top
UNK2GND11  TP01  [TP_040_T]  85.24 249.81 0 top
UNK2GND12  TP01  [TP_040_T]  513.5 295.27 180 top
UNK2GND13  TP01  [TP_040_T]  496.99 278.76 180 top
UNK2GND14  TP01  [TP_040_T]  466.94 278.76 0 top
UNK2J1  HDR-2X1-M  [JP_2P_100]  468.63 233.43 90 bottom
UNK2J2  HDR-3X1-M  [JP_3P_100]  490.87 228.66 270 bottom
UNK2J3  HDR-3X1-M  [JP_3P_100]  490.87 214.94 270 bottom
UNK2J4  HDR-2X1-M  [JP_2P_100]  483.11 243.33 270 bottom
UNK2J5  HDR-2X1-M  [JP_2P_100]  483.11 231.65 270 bottom
UNK2K1  G6K-2F-RF-T-5V-SPECIAL  [RL_G6K2FRT_8P_5V_GR]  414.27 293.12 0 bottom
UNK2K2  G6K-2F-RF-T-5V-SPECIAL  [RL_G6K2FRT_8P_5V_GR]  373.13 245.11 0 bottom
UNK2K3  G6K-2F-RF-T-5V-SPECIAL  [RL_G6K2FRT_8P_5V_GR]  400.3 261.37 0 bottom
UNK2K4  G6K-2F-RF-T-5V-SPECIAL  [RL_G6K2FRT_8P_5V_GR]  373.13 261.11 0 bottom
UNK2K5  G6K-2F-RF-T-5V-SPECIAL  [RL_G6K2FRT_8P_5V_GR]  414.02 261.37 0 bottom
UNK2K6  G6K-2F-RF-T-5V-SPECIAL  [RL_G6K2FRT_8P_5V_GR]  414.27 277.37 0 bottom
UNK2K7  G6K-2F-RF-T-5V-SPECIAL  [RL_G6K2FRT_8P_5V_GR]  400.3 277.11 0 bottom
UNK2K8  G6K-2F-RF-T-5V-SPECIAL  [RL_G6K2FRT_8P_5V_GR]  386.84 293.12 0 bottom
UNK2K9  UA2-5NJ-A-V3  [RL_NECUA2_5V_V3]  299.96 235.46 90 bottom
UNK2K10  UA2-5NJ-A-V3  [RL_NECUA2_5V_V3]  467.11 228.6 180 bottom
UNK2K11  G6K-2F-RF-T-5V-SPECIAL  [RL_G6K2FRT_8P_5V_GR]  386.84 277.11 0 bottom
UNK2K12  UA2-5NJ-A-V3  [RL_NECUA2_5V_V3]  299.96 246.89 90 bottom
UNK2K13  UA2-5NJ-A-V3  [RL_NECUA2_5V_V3]  455.68 228.6 0 bottom
UNK2K14  UA2-5NJ-A-V3  [RL_NECUA2_5V_V3]  467.61 213.36 0 bottom
UNK2K15  UA2-5NJ-A-V3  [RL_NECUA2_5V_V3]  455.64 220.9 0 bottom
UNK2K16  G6K-2F-RF-T-5V-SPECIAL  [RL_G6K2FRT_8P_5V_GR]  373.38 277.11 0 bottom
UNK2K17  G6K-2F-RF-T-5V-SPECIAL  [RL_G6K2FRT_8P_5V_GR]  400.3 293.12 0 bottom
UNK2K18  UB2-5NU-B  [RL_NECUB2_5V]  308.45 274.32 0 bottom
UNK2K19  UA2-5NJ-A-V3  [RL_NECUA2_5V_V3]  467.61 220.98 0 bottom
UNK2K20  UA2-5NJ-A-V3  [RL_NECUA2_5V_V3]  455.68 213.36 0 bottom
UNK2K21  G6K-2F-RF-T-5V-SPECIAL  [RL_G6K2FRT_8P_5V_GR]  373.38 293.12 0 bottom
UNK2K22  G6K-2F-RF-T-5V-SPECIAL  [RL_G6K2FRT_8P_5V_GR]  400.3 229.11 0 bottom
UNK2K23  G6K-2F-RF-T-5V-SPECIAL  [RL_G6K2FRT_8P_5V_GR]  407.16 213.61 0 bottom
UNK2K24  G6K-2F-RF-T-5V-SPECIAL  [RL_G6K2FRT_8P_5V_GR]  393.45 213.36 0 bottom
UNK2K25  G6K-2F-RF-T-5V-SPECIAL  [RL_G6K2FRT_8P_5V_GR]  414.27 245.11 0 bottom
UNK2K26  G6K-2F-RF-T-5V-SPECIAL  [RL_G6K2FRT_8P_5V_GR]  373.13 228.6 0 bottom
UNK2K27  G6K-2F-RF-T-5V-SPECIAL  [RL_G6K2FRT_8P_5V_GR]  386.84 228.85 0 bottom
UNK2K28  UA2-5NJ-A-V3  [RL_NECUA2_5V_V3]  479.04 237.49 180 bottom
UNK2K29  G6K-2F-RF-T-5V-SPECIAL  [RL_G6K2FRT_8P_5V_GR]  386.84 245.11 0 bottom
UNK2K30  G6K-2F-RF-T-5V-SPECIAL  [RL_G6K2FRT_8P_5V_GR]  400.3 245.11 0 bottom
UNK2K31  EC2-5NJ-A  [RL_NECEC2_10P_5V]  506.73 294.64 90 bottom
UNK2K33  NC/UA2-5NJ-A-V3  [RL_NECUA2_5V_V3]  455.68 237.74 0 bottom
UNK2K34  EC2-5NJ-A  [RL_NECEC2_10P_5V]  457.2 294.64 90 bottom
UNK2K36  EC2-5NJ-A  [RL_NECEC2_10P_5V]  490.22 294.64 90 bottom
UNK2K37  EC2-5NJ-A  [RL_NECEC2_10P_5V]  457.2 278.13 90 bottom
UNK2K39  EC2-5NJ-A  [RL_NECEC2_10P_5V]  490.22 278.13 90 bottom
UNK2K40  EC2-5NJ-A  [RL_NECEC2_10P_5V]  473.71 294.64 90 bottom
UNK2K42  EC2-5NJ-A  [RL_NECEC2_10P_5V]  473.71 278.13 90 bottom
UNK2K43  G6K-2F-RF-T-5V-SPECIAL  [RL_G6K2FRT_8P_5V_GR]  386.84 261.11 0 bottom
UNK2R1  NC/1M-1-S4  [R0402]  301.23 227.84 180 bottom
UNK2R2  NC/1M-1-S4  [R0402]  298.95 227.84 0 bottom
UNK2R3  NC/100K-1-S4  [R0402]  289.81 130.81 180 bottom
UNK2R4  NC/100K-1-S4  [R0402]  287.27 130.81 180 bottom
UNK2R5  0-5-S4  [R0402]  302.38 272.16 270 bottom
UNK2R6  1M-1-S4  [R0402]  302.38 274.32 270 bottom
UNK2R7  49.9-1-S4  [R0402]  415.95 299.91 180 bottom
UNK2R8  49.9-1-S4  [R0402]  418.1 299.91 180 bottom
UNK2R9  49.9-1-S4  [R0402]  415.95 286.32 180 bottom
UNK2R10  49.9-1-S4  [R0402]  418.1 286.32 180 bottom
UNK2R11  49.9-1-S4  [R0402]  374.8 251.9 180 bottom
UNK2R12  49.9-1-S4  [R0402]  376.95 251.9 180 bottom
UNK2R13  49.9-1-S4  [R0402]  374.8 238.32 180 bottom
UNK2R14  49.9-1-S4  [R0402]  376.95 238.32 180 bottom
UNK2R15  49.9-1-S4  [R0402]  401.98 268.16 180 bottom
UNK2R16  49.9-1-S4  [R0402]  404.13 268.16 180 bottom
UNK2R17  49.9-1-S4  [R0402]  401.98 254.57 180 bottom
UNK2R18  49.9-1-S4  [R0402]  404.13 254.57 180 bottom
UNK2R19  49.9-1-S4  [R0402]  374.8 267.91 180 bottom
UNK2R20  49.9-1-S4  [R0402]  376.95 267.91 180 bottom
UNK2R21  49.9-1-S4  [R0402]  374.8 254.32 180 bottom
UNK2R22  49.9-1-S4  [R0402]  376.95 254.32 180 bottom
UNK2R23  49.9-1-S4  [R0402]  415.7 268.16 180 bottom
UNK2R24  49.9-1-S4  [R0402]  417.84 268.16 180 bottom
UNK2R25  49.9-1-S4  [R0402]  415.7 254.57 180 bottom
UNK2R26  49.9-1-S4  [R0402]  417.84 254.57 180 bottom
UNK2R27  49.9-1-S4  [R0402]  415.95 284.16 180 bottom
UNK2R28  49.9-1-S4  [R0402]  418.1 284.16 180 bottom
UNK2R29  49.9-1-S4  [R0402]  415.95 270.57 180 bottom
UNK2R30  49.9-1-S4  [R0402]  418.1 270.57 180 bottom
UNK2R31  49.9-1-S4  [R0402]  401.98 283.91 180 bottom
UNK2R32  49.9-1-S4  [R0402]  404.13 283.91 180 bottom
UNK2R33  49.9-1-S4  [R0402]  401.98 270.32 180 bottom
UNK2R34  49.9-1-S4  [R0402]  404.13 270.32 180 bottom
UNK2R37  49.9-1-S4  [R0402]  388.52 286.32 180 bottom
UNK2R38  49.9-1-S4  [R0402]  390.66 286.32 180 bottom
UNK2R39  49.9-1-S4  [R0402]  388.52 283.91 180 bottom
UNK2R40  49.9-1-S4  [R0402]  390.66 283.91 180 bottom
UNK2R41  49.9-1-S4  [R0402]  388.52 270.32 180 bottom
UNK2R42  49.9-1-S4  [R0402]  390.66 270.32 180 bottom
UNK2R43  49.9-1-S4  [R0402]  388.52 238.32 180 bottom
UNK2R44  49.9-1-S4  [R0402]  390.66 238.32 180 bottom
UNK2R45  49.9-1-S4  [R0402]  401.98 222.31 180 bottom
UNK2R46  49.9-1-S4  [R0402]  404.13 222.31 180 bottom
UNK2R47  49.9-1-S4  [R0402]  408.84 220.41 180 bottom
UNK2R48  49.9-1-S4  [R0402]  410.98 220.41 180 bottom
UNK2R49  49.9-1-S4  [R0402]  408.84 206.82 180 bottom
UNK2R50  49.9-1-S4  [R0402]  410.98 206.82 180 bottom
UNK2R51  49.9-1-S4  [R0402]  395.12 220.15 180 bottom
UNK2R52  49.9-1-S4  [R0402]  397.27 220.15 180 bottom
UNK2R53  49.9-1-S4  [R0402]  395.12 206.57 180 bottom
UNK2R54  49.9-1-S4  [R0402]  397.27 206.57 180 bottom
UNK2R55  49.9-1-S4  [R0402]  415.95 251.9 180 bottom
UNK2R56  49.9-1-S4  [R0402]  418.1 251.9 180 bottom
UNK2R57  49.9-1-S4  [R0402]  415.95 238.32 180 bottom
UNK2R58  49.9-1-S4  [R0402]  418.1 238.32 180 bottom
UNK2R59  49.9-1-S4  [R0402]  374.8 235.39 180 bottom
UNK2R60  49.9-1-S4  [R0402]  376.95 235.39 180 bottom
UNK2R61  49.9-1-S4  [R0402]  374.8 221.81 180 bottom
UNK2R62  49.9-1-S4  [R0402]  376.95 221.81 180 bottom
UNK2R63  49.9-1-S4  [R0402]  401.98 251.9 180 bottom
UNK2R64  49.9-1-S4  [R0402]  404.13 251.9 180 bottom
UNK2R65  49.9-1-S4  [R0402]  388.52 222.06 180 bottom
UNK2R66  49.9-1-S4  [R0402]  390.66 222.06 180 bottom
UNK2R67  49.9-1-S4  [R0402]  375.06 283.91 180 bottom
UNK2R68  49.9-1-S4  [R0402]  377.2 283.91 180 bottom
UNK2R69  49.9-1-S4  [R0402]  375.06 270.32 180 bottom
UNK2R70  49.9-1-S4  [R0402]  377.2 270.32 180 bottom
UNK2R71  49.9-1-S4  [R0402]  401.98 299.91 180 bottom
UNK2R72  49.9-1-S4  [R0402]  404.13 299.91 180 bottom
UNK2R73  49.9-1-S4  [R0402]  401.98 286.32 180 bottom
UNK2R74  49.9-1-S4  [R0402]  404.13 286.32 180 bottom
UNK2R75  49.9-1-S4  [R0402]  375.06 299.91 180 bottom
UNK2R76  49.9-1-S4  [R0402]  377.2 299.91 180 bottom
UNK2R77  49.9-1-S4  [R0402]  375.06 286.32 180 bottom
UNK2R78  49.9-1-S4  [R0402]  377.2 286.32 180 bottom
UNK2R79  49.9-1-S4  [R0402]  388.52 251.9 180 bottom
UNK2R80  49.9-1-S4  [R0402]  390.66 251.9 180 bottom
UNK2R82  4.7K-1-S4-WA  [R0402]  456.75 233.88 0 bottom
UNK2R83  4.7K-1-S4-WA  [R0402]  482.6 241.3 0 bottom
UNK2R84  4.7K-1-S4-WA  [R0402]  482.6 233.68 0 bottom
UNK2R85  100K-1-S4  [R0402]  465.07 235.71 0 bottom
UNK2R86  4.7K-1-S4-WA  [R0402]  486.3 226.62 0 bottom
UNK2R87  4.7K-1-S4-WA  [R0402]  475.49 230.78 0 bottom
UNK2R88  4.7K-1-S4-WA  [R0402]  478.03 230.78 0 bottom
UNK2R89  4.7K-1-S4-WA  [R0402]  490.6 226.67 180 bottom
UNK2R90  4.7K-1-S4-WA  [R0402]  478.03 218.59 0 bottom
UNK2R91  4.7K-1-S4-WA  [R0402]  480.57 218.59 0 bottom
UNK2R92  4.7K-1-S4-WA  [R0402]  483.11 218.59 0 bottom
UNK2R93  4.7K-1-S4-WA  [R0402]  486.3 212.91 0 bottom
UNK2R94  4.7K-1-S4-WA  [R0402]  475.37 217.23 180 bottom
UNK2R95  4.7K-1-S4-WA  [R0402]  477.93 217.17 0 bottom
UNK2R96  4.7K-1-S4-WA  [R0402]  490.36 212.91 180 bottom
UNK2R97  4.7K-1-S4-WA  [R0402]  477.93 204.98 0 bottom
UNK2R98  4.7K-1-S4-WA  [R0402]  480.47 204.98 0 bottom
UNK2R99  4.7K-1-S4-WA  [R0402]  483.01 204.98 0 bottom
UNK2R100  49.9-1-S4  [R0402]  401.98 238.32 180 bottom
UNK2R101  49.9-1-S4  [R0402]  404.13 238.32 180 bottom
UNK2R102  49.9-1-S4  [R0402]  401.98 235.9 180 bottom
UNK2R103  49.9-1-S4  [R0402]  404.13 235.9 180 bottom
UNK2R104  49.9-1-S4  [R0402]  388.52 235.65 180 bottom
UNK2R105  49.9-1-S4  [R0402]  390.66 235.65 180 bottom
UNK2R117  1K-1-S4  [R0402]  452.18 233.88 0 bottom
UNK2R118  NC/0-5-S4  [R0402]  310.41 245.39 180 bottom
UNK2R119  4.7K-1-S4-WA  [R0402]  452.12 224.79 180 bottom
UNK2R120  4.7K-1-S4-WA  [R0402]  452.12 232.41 180 bottom
UNK2R125  0-5-S4  [R0402]  456.44 209.55 0 bottom
UNK2R126  0-5-S4  [R0402]  452.37 209.55 0 bottom
UNK2R127  0-5-S4  [R0402]  456.69 217.17 0 bottom
UNK2R128  0-5-S4  [R0402]  452.12 217.17 0 bottom
UNK2R129  0-5-S4  [R0402]  301.23 229.11 180 bottom
UNK2R130  0-5-S4  [R0402]  298.95 229.11 0 bottom
UNK2R131  50-0.1-S4-HF-VI  [R0402]  303.77 243.33 90 bottom
UNK2R132  50-0.1-S4-HF-VI  [R0402]  296.15 243.33 90 bottom
UNK2R133  0-5-S4  [R0402]  302.38 276.48 90 bottom
UNK2SH1  SHORT  [DEFAULT_SHORT_SMALL]  462.05 291.99 0 top
UNK2SH2  SHORT  [DEFAULT_SHORT_SMALL]  464 291.99 0 top
UNK2SH3  SHORT  [DEFAULT_SHORT_SMALL]  452.21 291.99 0 top
UNK2SH4  SHORT  [DEFAULT_SHORT_SMALL]  450.26 292.12 180 top
UNK2SH5  SHORT  [DEFAULT_SHORT_SMALL]  485.23 291.99 0 top
UNK2SH6  SHORT  [DEFAULT_SHORT_SMALL]  483.28 292.12 180 top
UNK2SH7  SHORT  [DEFAULT_SHORT_SMALL]  462.05 275.48 0 top
UNK2SH8  SHORT  [DEFAULT_SHORT_SMALL]  450.26 275.61 180 top
UNK2SH9  SHORT  [DEFAULT_SHORT_SMALL]  464 275.48 0 top
UNK2SH10  SHORT  [DEFAULT_SHORT_SMALL]  452.21 275.48 0 top
UNK2SH11  SHORT  [DEFAULT_SHORT_SMALL]  483.28 275.61 180 top
UNK2SH12  SHORT  [DEFAULT_SHORT_SMALL]  495.07 275.48 0 top
UNK2SH13  SHORT  [DEFAULT_SHORT_SMALL]  480.51 291.99 0 top
UNK2SH14  SHORT  [DEFAULT_SHORT_SMALL]  478.56 291.99 0 top
UNK2SH15  SHORT  [DEFAULT_SHORT_SMALL]  466.77 292.12 180 top
UNK2SH16  SHORT  [DEFAULT_SHORT_SMALL]  468.72 291.99 0 top
UNK2SH17  SHORT  [DEFAULT_SHORT_SMALL]  466.77 275.61 180 top
UNK2SH18  SHORT  [DEFAULT_SHORT_SMALL]  478.56 275.48 0 top
UNK2SH19  SHORT  [DEFAULT_SHORT_SMALL]  90.17 246.75 0 top
UNK2SH20  SHORT  [DEFAULT_SHORT_SMALL]  92.37 246.75 0 top
UNK2SH21  SHORT  [DEFAULT_SHORT_SMALL]  85.31 246.8 0 top
UNK2SH22  SHORT  [DEFAULT_SHORT_SMALL]  87.51 246.8 0 top
UNK2SH23  SHORT  [DEFAULT_SHORT_SMALL]  511.58 291.99 0 top
UNK2SH24  SHORT  [DEFAULT_SHORT_SMALL]  513.76 291.86 180 top
UNK2SH25  SHORT  [DEFAULT_SHORT_SMALL]  485.23 275.48 0 top
UNK2SH26  SHORT  [DEFAULT_SHORT_SMALL]  497.02 275.48 0 top
UNK2SH27  SHORT  [DEFAULT_SHORT_SMALL]  468.72 275.48 0 top
UNK2SH28  SHORT  [DEFAULT_SHORT_SMALL]  480.51 275.48 0 top
UNK2TP_AUXVCC  TP01  [TP_040_T]  92.04 247.9 180 top
UNK2TP_AVDD11_RX  TP01  [TP_040_T]  452.33 276.86 180 top
UNK2TP_AVDD11_XTAL  TP01  [TP_040_T]  511.6 293.37 0 top
UNK2TP_AVDD18_RX  TP01  [TP_040_T]  462.07 276.86 0 top
UNK2TP_PLL_M_VDD33  TP01  [TP_040_T]  478.58 293.37 0 top
UNK2TP_PLL_TX_VDD33  TP01  [TP_040_T]  468.84 293.37 180 top
UNK2TP_VCC3V3  TP01  [TP_040_T]  87.17 247.96 180 top
UNK2TP_VDD_IO_33  TP01  [TP_040_T]  452.33 293.37 180 top
UNK2TP_VDD_TXREG_33_B  TP01  [TP_040_T]  478.58 276.86 0 top
UNK2TP_VDD_TXREG_33_T  TP01  [TP_040_T]  468.84 276.86 180 top
UNK2TP_VDDA_33_LV  TP01  [TP_040_T]  462.07 293.37 0 top
UNK2TP_VDDC_11  TP01  [TP_040_T]  485.35 293.37 180 top
UNK2TP_VDDTXPST_11_B  TP01  [TP_040_T]  495.09 276.86 0 top
UNK2TP_VDDTXPST_11_T  TP01  [TP_040_T]  485.35 276.86 180 top
UNK2TP_XTAL_IN  TP01  [TP_040_T]  306.85 271.67 0 top
UNK2TP_XTAL_OUT  TP01  [TP_040_T]  306.85 276.97 0 top
UNK2U1  SOLDER-DIP8-SOCKET  [DIP8_300X100_RLPIN]  474.97 228.55 270 bottom
UNK2U2  SOLDER-DIP8-SOCKET  [DIP8_300X100_RLPIN]  474.87 214.94 270 bottom
UNK2UF1  MX25L4006EM2I-12G-SOP8  [SOCKET_CODE]  360.09 283.74 180 top
UNK2UF2  MX25L4006EM2I-12G-SOP8  [SOCKET_CODE]  474.97 228.55 90 top
UNK2Y1  XTAL27M-S2520-ABRACON-10P  [XTAL_2X2P5MM_4P]  298.76 274.89 270 bottom
UNK2Y2  NC/XTAL27M-S3225-TXC-10P  [XTAL_3P2X2P5MM_4P_TXC_0201]  298.76 274.89 270 bottom
UNK3C3  0.1U-16-X-S4-MU  [C0402]  192.28 132.33 180 bottom
UNK3C4  0.1U-16-X-S4-MU  [C0402]  189.74 132.33 180 bottom
UNK3C5  22P-50-N-S4-AVX  [C0402]  221.21 217.48 90 bottom
UNK3C6  22P-50-N-S4-AVX  [C0402]  221.21 211.16 270 bottom
UNK3C7  0.1U-16-X-S4-MU  [C0402]  111 186.44 0 bottom
UNK3C8  0.1U-16-X-S4-MU  [C0402]  104.39 171.81 180 bottom
UNK3C9  0.1U-16-X-S4-MU  [C0402]  104.49 185.42 180 bottom
UNK3CA1  NC/10U-10-X6S-S6-MU  [C0603]  112.39 290.83 0 bottom
UNK3CA2  NC/47U-10-X5R-S8-TDK  [C0805]  112.5 292.74 0 bottom
UNK3CA3  NC/10U-10-X6S-S6-MU  [C0603]  100.96 290.83 180 bottom
UNK3CA4  NC/47U-10-X5R-S8-TDK  [C0805]  100.86 292.74 180 bottom
UNK3CA5  NC/10U-10-X6S-S6-MU  [C0603]  100.96 274.32 180 bottom
UNK3CA6  NC/47U-10-X5R-S8-TDK  [C0805]  100.86 276.23 180 bottom
UNK3CA7  NC/10U-10-X6S-S6-MU  [C0603]  128.9 274.32 0 bottom
UNK3CA8  NC/47U-10-X5R-S8-TDK  [C0805]  129.01 276.23 0 bottom
UNK3CA9  NC/10U-10-X6S-S6-MU  [C0603]  117.47 274.32 180 bottom
UNK3CA10  NC/47U-10-X5R-S8-TDK  [C0805]  117.37 276.23 180 bottom
UNK3CA11  NC/10U-10-X6S-S6-MU  [C0603]  76.83 290.83 0 bottom
UNK3CA12  NC/47U-10-X5R-S8-TDK  [C0805]  76.94 292.74 0 bottom
UNK3CA13  NC/47U-10-X5R-S8-TDK  [C0805]  94.72 292.74 0 bottom
UNK3CA14  NC/10U-10-X6S-S6-MU  [C0603]  94.61 290.83 0 bottom
UNK3CA15  NC/47U-10-X5R-S8-TDK  [C0805]  83.08 292.74 180 bottom
UNK3CA16  NC/10U-10-X6S-S6-MU  [C0603]  83.18 290.83 180 bottom
UNK3CA17  NC/47U-10-X5R-S8-TDK  [C0805]  76.94 276.23 0 bottom
UNK3CA18  NC/10U-10-X6S-S6-MU  [C0603]  76.83 274.32 0 bottom
UNK3CA19  NC/47U-10-X5R-S8-TDK  [C0805]  111.1 249.13 180 bottom
UNK3CA20  NC/10U-10-X6S-S6-MU  [C0603]  111.2 247.23 180 bottom
UNK3CA21  10U-10-X6S-S6-MU  [C0603]  112.39 288.29 0 bottom
